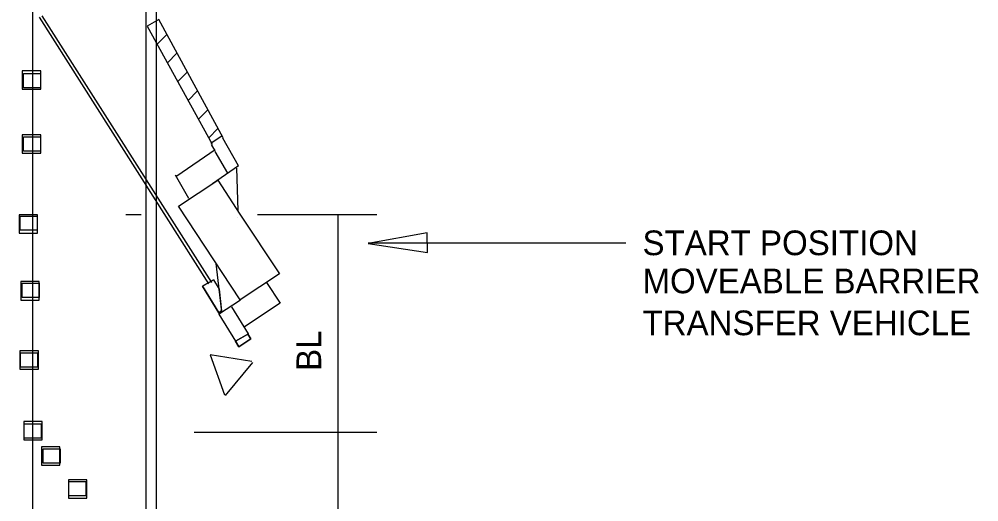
# Model space of a CAD drawing. Extents: x 54531.5 to 54538.4, y 53883.4 to 53893.4.
# Drawn here: x 54535.32 to 54537.651, y 53888.735 to 53889.908 of the extents above; entities that cross this region are included whole.
import ezdxf

# ---------------------------------------------------------------- set-up
doc = ezdxf.new("R2010")
doc.units = 0
for name, color, linetype in [('DETL-DIMS', 7, 'Continuous'), ('DETL-LINE', 7, 'Continuous'), ('DETL-NOTE', 7, 'Continuous')]:
    doc.layers.add(name, color=color, linetype=linetype)

msp = doc.modelspace()

# ---------------------------------------------------------------- linework, layer by layer
at = {"layer": 'DETL-DIMS'}
for p, q in [((54535.8994, 53889.4335), (54536.1886, 53889.4335)), ((54536.0947, 53885.8311), (54536.0947, 53889.4335)), ((54536.1674, 53889.3643), (54536.7939, 53889.3643)), ((54535.7451, 53888.904), (54536.1886, 53888.904))]:
    msp.add_line(p, q, dxfattribs=at)
msp.add_lwpolyline([(54536.3117, 53889.3405), (54536.3111, 53889.3885), (54536.1674, 53889.3624)], close=True, dxfattribs=at)
at = {"layer": 'DETL-LINE'}
for p, q in [((54535.3526, 53892.5314), (54535.3526, 53885.9139)), ((54535.6275, 53892.5314), (54535.6275, 53889.7593)), ((54535.6526, 53891.0235), (54535.6526, 53885.946)), ((54535.3685, 53889.9128), (54535.7804, 53889.265)), ((54535.3751, 53889.916), (54535.787, 53889.2683)), ((54535.6591, 53889.9068), (54535.6312, 53889.8908)), ((54535.8153, 53889.6192), (54535.6591, 53889.9068)), ((54535.6312, 53889.8908), (54535.7891, 53889.6043)), ((54535.6551, 53889.8474), (54535.6786, 53889.8708)), ((54535.6802, 53889.8018), (54535.7035, 53889.825)), ((54535.6275, 53889.7685), (54535.6275, 53885.946)), ((54535.7053, 53889.7562), (54535.7283, 53889.7792)), ((54535.7304, 53889.7106), (54535.7532, 53889.7334)), ((54535.7555, 53889.665), (54535.7782, 53889.6876)), ((54535.7807, 53889.6194), (54535.8031, 53889.6418)), ((54535.8129, 53889.6247), (54535.7859, 53889.606)), ((54535.7868, 53889.603), (54535.7955, 53889.5876)), ((54535.8528, 53889.5512), (54535.8145, 53889.6188)), ((54535.7029, 53889.5274), (54535.7959, 53889.5915)), ((54535.8266, 53889.5332), (54535.7963, 53889.5864)), ((54535.7325, 53889.472), (54535.7002, 53889.529)), ((54535.8528, 53889.5512), (54535.7895, 53889.5076)), ((54535.8477, 53889.5461), (54535.8511, 53889.4426)), ((54535.7069, 53889.4531), (54535.8024, 53889.5162)), ((54535.8024, 53889.5162), (54535.8565, 53889.4343)), ((54535.8573, 53889.2255), (54535.7069, 53889.4531)), ((54535.5791, 53889.4335), (54535.6166, 53889.4335)), ((54535.8514, 53889.4257), (54535.8514, 53889.4257)), ((54535.8565, 53889.4343), (54535.9528, 53889.2886)), ((54535.8123, 53889.1966), (54535.7985, 53889.3144)), ((54535.7924, 53889.274), (54535.7651, 53889.2586)), ((54535.7924, 53889.274), (54535.8058, 53889.2516)), ((54535.9528, 53889.2886), (54535.8573, 53889.2255)), ((54535.7651, 53889.2586), (54535.805, 53889.1944)), ((54535.921, 53889.2676), (54535.954, 53889.2176)), ((54535.8046, 53889.1908), (54535.8574, 53889.2256)), ((54535.8768, 53889.1432), (54535.8364, 53889.2088)), ((54535.954, 53889.2176), (54535.8673, 53889.1602)), ((54535.805, 53889.1944), (54535.812, 53889.199)), ((54535.805, 53889.191), (54535.8457, 53889.1255)), ((54535.8768, 53889.1432), (54535.8453, 53889.1253)), ((54535.8827, 53889.1306), (54535.8759, 53889.1427)), ((54535.8453, 53889.1253), (54535.8538, 53889.1118)), ((54535.8538, 53889.1118), (54535.8827, 53889.1306)), ((54535.7842, 53889.0924), (54535.819, 53888.9951)), ((54535.8854, 53889.0759), (54535.7842, 53889.0924)), ((54535.8873, 53889.0732), (54535.8207, 53888.9931))]:
    msp.add_line(p, q, dxfattribs=at)
for points in [[(54535.3526, 53889.9514), (54535.3526, 53889.8314)], [(54535.3526, 53889.4714), (54535.3526, 53889.3514)], [(54535.3526, 53888.9914), (54535.3526, 53888.8714)]]:
    msp.add_lwpolyline(points, dxfattribs=at)
for points in [[(54535.3278, 53889.7374), (54535.3726, 53889.7374), (54535.3726, 53889.7822), (54535.3278, 53889.7822)], [(54535.331, 53889.7412), (54535.331, 53889.7759), (54535.3722, 53889.7759), (54535.3722, 53889.7412)], [(54535.3278, 53889.5823), (54535.3726, 53889.5823), (54535.3726, 53889.6271), (54535.3278, 53889.6271)], [(54535.331, 53889.5873), (54535.331, 53889.622), (54535.3722, 53889.622), (54535.3722, 53889.5873)], [(54535.3203, 53889.3879), (54535.3651, 53889.3879), (54535.3651, 53889.4327), (54535.3203, 53889.4327)], [(54535.3229, 53889.3948), (54535.3229, 53889.4295), (54535.3641, 53889.4295), (54535.3641, 53889.3948)], [(54535.7651, 53889.2586), (54535.7924, 53889.274), (54535.8058, 53889.2516), (54535.812, 53889.199), (54535.805, 53889.1944)], [(54535.3241, 53889.2253), (54535.3689, 53889.2253), (54535.3689, 53889.2701), (54535.3241, 53889.2701)], [(54535.3279, 53889.2317), (54535.3279, 53889.2664), (54535.3691, 53889.2664), (54535.3691, 53889.2317)], [(54535.8453, 53889.1253), (54535.8759, 53889.1427), (54535.8827, 53889.1306), (54535.8538, 53889.1118)], [(54535.3222, 53889.0572), (54535.367, 53889.0572), (54535.367, 53889.102), (54535.3222, 53889.102)], [(54535.3232, 53889.0622), (54535.3232, 53889.0968), (54535.3644, 53889.0968), (54535.3644, 53889.0622)], [(54535.3315, 53888.8854), (54535.3763, 53888.8854), (54535.3763, 53888.9302), (54535.3315, 53888.9302)], [(54535.3327, 53888.89), (54535.3327, 53888.9247), (54535.3739, 53888.9247), (54535.3739, 53888.89)], [(54535.3745, 53888.8237), (54535.4193, 53888.8237), (54535.4193, 53888.8685), (54535.3745, 53888.8685)], [(54535.3787, 53888.829), (54535.3787, 53888.8636), (54535.4199, 53888.8636), (54535.4199, 53888.829)], [(54535.4398, 53888.7434), (54535.4846, 53888.7434), (54535.4846, 53888.7882), (54535.4398, 53888.7882)], [(54535.4411, 53888.7496), (54535.4411, 53888.7842), (54535.4823, 53888.7842), (54535.4823, 53888.7496)]]:
    msp.add_lwpolyline(points, close=True, dxfattribs=at)

# ---------------------------------------------------------------- texts
at = {"layer": 'DETL-NOTE'}
for s, p in [('START POSITION', (54536.8341, 53889.3343)), ('MOVEABLE BARRIER', (54536.8341, 53889.2418)), ('TRANSFER VEHICLE', (54536.8341, 53889.1398))]:
    msp.add_text(s, height=0.06, dxfattribs=at).set_placement(p)
msp.add_text('BL', height=0.06, rotation=90, dxfattribs=at).set_placement((54536.0537, 53889.0531))

doc.saveas('drawing.dxf')
